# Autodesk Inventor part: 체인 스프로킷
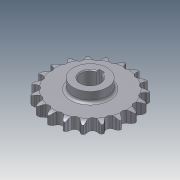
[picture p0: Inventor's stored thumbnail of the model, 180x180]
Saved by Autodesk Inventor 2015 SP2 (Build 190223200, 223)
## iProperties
Created: 2013-01
Part Number: 체인 스프로킷
Material: 강
Document SubType Name: Modeling
Designer: KYOUNG IL JANG
Density: 1 g/cm^3
Appearance: 강철
CustomPartVersion: 1
Company: 한국ATC센터
Author: KYOUNG IL JANG
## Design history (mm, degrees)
sketch "이론적 톱니 프로파일"
  geometry: L1 (0, 0)-(0, 45.567); L2 (0, 0)-(14.795, 43.098); L3 (0, 45.567)-(14.795, 43.098); L4 (0, 45.567)-(5.661, 50.015); L5 (5.661, 50.015)-(-5.141, 45.406); L6 (-12.428, 43.493)-(-5.573, 46.417); L7 (-5.141, 45.406)-(-5.573, 46.417); L8 (5.573, 46.417)-(5.141, 45.406); L9 (0, 0)-(8.138, 48.771); A1 r 45.567 centre (0, 0) between (0, 45.567) and (14.795, 43.098); A2 r 49.445 centre (0, 0) between (7.302, 48.903) and (-7.302, 48.903); A3 r 4.545 centre (0, 45.567) between (-3.574, 42.758) and (3.574, 42.758); A4 r 7.453 centre (12.428, 43.493) between (7.302, 48.903) and (5.573, 46.417); A5 r 7.453 centre (-12.428, 43.493) between (-5.573, 46.417) and (-7.302, 48.903); A6 r 11.745 centre (5.661, 50.015) between (-5.141, 45.406) and (-3.574, 42.758); A7 r 11.745 centre (-5.661, 50.015) between (3.574, 42.758) and (5.141, 45.406); 2 further points
  constraints: 18 end point, 15 point on circle, 7 centre point, 3 coincident, 3 point on line, 3 symmetric about line, 3 tangent, 1 equal radius, 1 midpoint, 1 parallel, 1 vertical, 1 other
  dimensions: "d0" = 91.13301 diameter of A1 (computed from da_p, da_z); "d2" = 18.9474 deg angle of L2 L1 (computed from da_z); "d3" = 4.545 radius of A3 (= 0.5 x da_Dr + da_SC); "d10" = 128.158 deg angle of L4 L1 (computed from da_z); "d11" = 15.0526 deg angle of L5 L4 (computed from da_z); "d12" = 7.2 distance of L3.start L4.end (= 0.8 x da_Dr); "d13" = 11.745 distance of L4.end L5.end (= 1.3 x da_Dr + da_SC); "d14" = 12.6 distance of A4.centre L1.end (= 1.4 x da_Dr); "d23" = 4.5 distance from line of L9.end L3 (= da_Ha)
sketch "톱니 프로파일"
  geometry: L1 (0, 0)-(0, 45.567); L2 (0, 45.567)-(4.203, 43.837); L3 (0, 45.567)-(-4.203, 43.837); A1 r 4.545 centre (0, 45.567) between (-4.203, 43.837) and (4.203, 43.837); A2 r 22.68 centre (25.176, 35.206) between (7.12, 48.93) and (4.203, 43.837); A3 r 22.68 centre (-25.176, 35.206) between (-4.203, 43.837) and (-7.12, 48.93); A4 r 49.445 centre (0, 0) between (-7.12, 48.93) and (7.12, 48.93) reference; 1 further point
  constraints: 9 point on circle, 6 end point, 3 centre point, 2 tangent, 1 coincident, 1 equal radius, 1 vertical, 1 other
  dimensions: "d44" = 135.263 deg angle of L3 L2 (= da_Alfa); "d45" = 22.68 radius of A2 (= da_Re); "d46" = 4.545 radius of A1 (= da_Ri)
sketch "단면 프로파일"
  geometry: L1 (49.445, 0)-(-49.445, 0) reference; L2 (33.265, 6.65)-(-33.265, 6.65); L3 (-33.265, 6.65)-(-33.265, -6.65); L4 (-33.265, -6.65)-(33.265, -6.65); L5 (33.265, -6.65)-(33.265, 6.65); L6 (33.265, 6.65)-(49.445, 6.65); L7 (49.445, 6.65)-(49.445, -6.65); L8 (49.445, -6.65)-(33.265, -6.65); L9 (33.265, -6.65)-(33.265, 6.65); L10 (42.183, 6.65)-(0, 6.65); L11 (0, 6.65)-(0, -6.65); L12 (0, -6.65)-(42.183, -6.65); L13 (0, 6.65)-(0, -6.65); L14 (49.445, 4.775)-(49.445, -4.775); A1 r 15 centre (42.183, -8.35) between (49.445, 4.775) and (42.183, 6.65); A2 r 15 centre (42.183, 8.35) between (42.183, -6.65) and (49.445, -4.775); 2 further points
  constraints: 26 end point, 7 midpoint, 5 perpendicular, 4 parallel, 4 point on circle, 3 point on line, 3 symmetric about line, 2 centre point, 2 horizontal, 2 tangent, 1 collinear, 1 other
  dimensions: "d30" = 13.3 distance between parallel lines of L8 L6 (= da_Bf); "d31" = 66.53007 distance between parallel lines of L3 L5 (= da_Ds); "d32" = 13.3 distance between parallel lines of L4 L2 (= da_Bs); "d33" = 1.875 distance from line of L14.start L6 (= da_Ba); "d34" = 15 radius of A1 (= da_Rx); "d43" = 6.65 distance between parallel lines of L4 L1 (computed from da_k, da_pt, da_Bs)
revolve "슈라우드" stored, may be unused: angle "d36" = 90 deg
revolve "스트랜드" stored, may be unused: angle "d37" = 90 deg
extrude "이론적 톱니" cut sketch "이론적 톱니 프로파일" stored distance "d18" = 10; taper "d19" = 0 deg; dims "d49" = 0, "form_type" = 0 [user parameter]
extrude "톱니" cut sketch "톱니 프로파일" stored distance "d47" = 10; taper "d48" = 0 deg; dims "d50" = 10, "form_type" = 0 [user parameter]
node "타이밍 평면"
node "작업 평면3"
sketch "스케치5"
  geometry: C1 r 20 at (0, -45.567); 1 further point
  constraints: 1 centre point, 1 coincident
  dimensions: "d52" = 40 diameter of C1
extrude "돌출4" join sketch "스케치5" stored distance "d53" = 10; taper "d54" = 0 deg
sketch "스케치6"
  geometry: L1 (3, 10.583)-(3, 13.8); L2 (3, 13.8)-(-3, 13.8); L3 (-3, 13.8)-(-3, 10.583); A1 r 11 centre (0, 0) between (3, 10.583) and (-3, 10.583); 1 further point
  constraints: 6 end point, 2 parallel, 2 point on circle, 1 centre point, 1 coincident, 1 perpendicular, 1 vertical
  dimensions: "d55" = 22 diameter of A1; "d56" = 24.8 dimension on A1 L2 (computed from d55); "d57" = 6 distance of L1.end L2.end
extrude "돌출5" cut sketch "스케치6" stored distance "d58" = 10; taper "d59" = 0 deg
fillet "모깎기2" dims "d60" = 3
chamfer "모따기1" distance "d61" = 1; stored, may be unused: second distance "d62" = 2, angle "d63" = 45 deg
body "Solid1"
pattern_linear "스트랜드 패턴" dims "d40" = 24 (= da_pt)
pattern_circular "톱니 패턴" dims angle "d21" = 360 deg
other parameters: "da_p" = 15 [user parameter; used in 1 equation term], "da_Dr" = 9 [user parameter; used in 4 equation terms], "da_SC" = 0.045 [user parameter; used in 2 equation terms], "da_Ha" = 4.5 [user parameter; used in 1 equation term], "da_pt" = 24 [user parameter; used in 2 equation terms], "da_Bf" = 13.3 [user parameter; used in 1 equation term], "d28" = 0, "d29" = 0, "da_Ba" = 1.875 [user parameter; used in 1 equation term], "da_Rx" = 15 [user parameter; used in 1 equation term], "da_Ra" = 0.6 [user parameter], "da_Bs" = 13.3 [user parameter; used in 2 equation terms], "da_Ds" = 66.53007 [user parameter; used in 1 equation term], "d42" = 0, "da_Re" = 22.68 [user parameter; used in 1 equation term], "da_Ri" = 4.545 [user parameter; used in 1 equation term], "da_Alfa" = 135.263 deg [user parameter; used in 1 equation term], "d51" = -25
